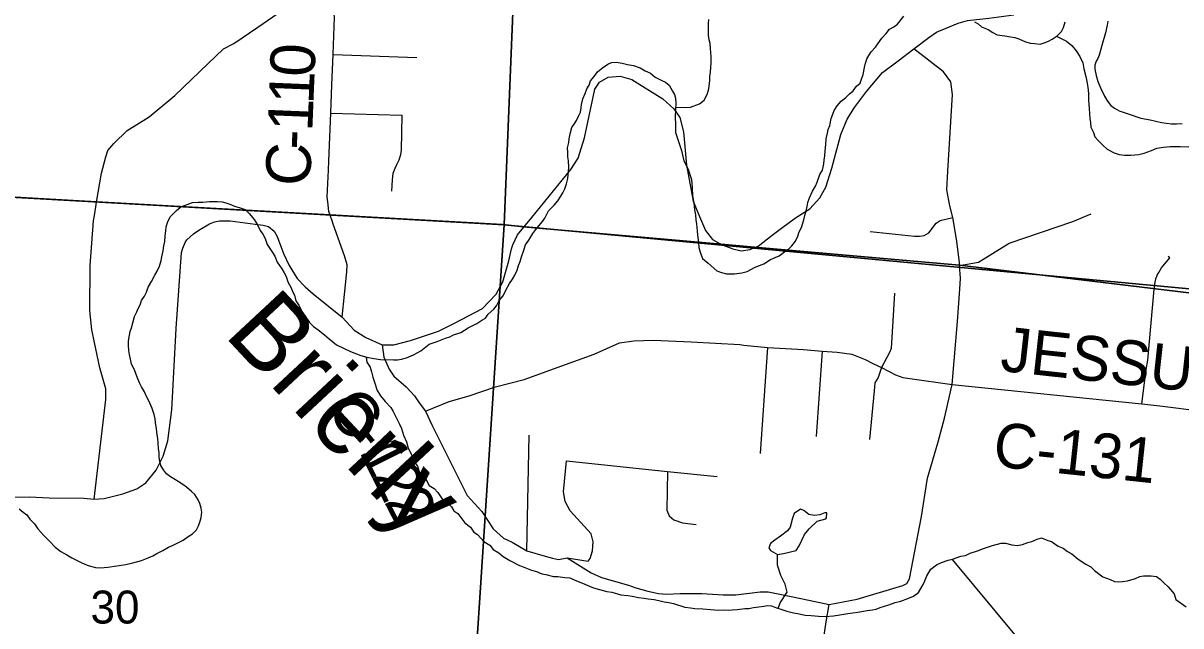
# Model space of a CAD drawing. Extents: x 0 to 34, y 0 to 22.
# Drawn here: x 6.66 to 8.131, y 16.534 to 17.301 of the extents above; entities that cross this region are included whole.
import ezdxf

# ---------------------------------------------------------------- set-up
doc = ezdxf.new("R2010")
doc.units = 0
for name, color, linetype in [('GM_X_County_Road', 7, 'Continuous'), ('GM_X_County_Road_Text', 7, 'Continuous'), ('GM_X_Minor_Lake', 7, 'Continuous'), ('GM_X_Minor_River', 7, 'Continuous'), ('GM_X_Minor_River_Text', 7, 'Continuous'), ('GM_X_Section', 7, 'Continuous'), ('GM_X_Section_Text', 7, 'Continuous'), ('GM_X_State_Route', 7, 'Continuous'), ('GM_X_Township_Road', 7, 'Continuous')]:
    doc.layers.add(name, color=color, linetype=linetype)

msp = doc.modelspace()

# ---------------------------------------------------------------- linework, layer by layer
at = {"layer": 'GM_X_County_Road'}
for points in [[(7.0481, 17.1255), (7.0507, 17.1859), (7.0521, 17.2223), (7.0536, 17.2608), (7.0555, 17.3082), (7.0537, 17.3227), (7.051, 17.3335)], [(6.752, 17.067), (6.753, 17.073), (6.759, 17.1097), (6.7646, 17.1304), (6.7671, 17.1386), (6.775, 17.1475), (6.7918, 17.1639), (6.8199, 17.1814), (6.8523, 17.2085), (6.8942, 17.249), (6.9143, 17.268), (6.9274, 17.2748), (6.958, 17.2954), (6.9892, 17.3172)], [(7.8237, 17.2902), (7.8331, 17.2941), (7.8482, 17.3004), (7.86, 17.3037), (7.8873, 17.3067), (7.9192, 17.3109)], [(8.0384, 17.303), (8.0378, 17.2981), (8.0356, 17.288), (8.0309, 17.2723), (8.0275, 17.2599), (8.0258, 17.2555), (8.0238, 17.2521), (8.0221, 17.2469), (8.0219, 17.242), (8.0236, 17.234), (8.0259, 17.2264), (8.0298, 17.2175), (8.0343, 17.2075), (8.0379, 17.2014), (8.0423, 17.1959), (8.047, 17.1924), (8.053, 17.1891), (8.0642, 17.1853), (8.0806, 17.1798), (8.0922, 17.1775), (8.1068, 17.174), (8.1196, 17.1724), (8.1257, 17.1726), (8.1332, 17.1731)], [(7.792, 17.2678), (7.8108, 17.2823), (7.8209, 17.289), (7.8237, 17.2902)], [(7.2806, 17.0137), (7.2819, 17.0188), (7.288, 17.0315), (7.296, 17.0411), (7.3061, 17.0533), (7.3559, 17.1144), (7.3651, 17.1289), (7.3731, 17.1548), (7.3865, 17.2167), (7.3921, 17.2256), (7.4033, 17.2317), (7.4185, 17.2331), (7.4332, 17.2289), (7.4726, 17.2044), (7.4866, 17.1915), (7.4945, 17.1806), (7.4989, 17.1622), (7.5028, 17.1199), (7.5112, 17.0741), (7.5196, 17.0548), (7.527, 17.0371), (7.5361, 17.0254), (7.5473, 17.019), (7.5619, 17.0136), (7.5724, 17.011), (7.5838, 17.0129), (7.5895, 17.0153), (7.5938, 17.0171), (7.6117, 17.031), (7.6238, 17.0397), (7.6413, 17.0532), (7.6598, 17.0644), (7.6724, 17.0784), (7.6801, 17.0922), (7.6877, 17.1162), (7.6989, 17.1588), (7.7072, 17.1783), (7.7164, 17.1932), (7.7318, 17.2136), (7.7519, 17.2376), (7.7721, 17.2525), (7.792, 17.2678)], [(7.8505, 16.9622), (7.8514, 16.9762), (7.8501, 16.9923), (7.8498, 16.9956), (7.8466, 17.0235), (7.8415, 17.0535), (7.8378, 17.0684), (7.8339, 17.0888), (7.8352, 17.1125), (7.8411, 17.21), (7.839, 17.226), (7.8297, 17.2386), (7.792, 17.2678)], [(7.0537, 17.0449), (7.0527, 17.0478), (7.0498, 17.0564), (7.0482, 17.0612), (7.0468, 17.0734), (7.0461, 17.0795), (7.0476, 17.1134), (7.0481, 17.1255)], [(6.7497, 16.6953), (6.7648, 16.822), (6.7645, 16.8357), (6.757, 16.8625), (6.7468, 16.9107), (6.7442, 16.9351), (6.7449, 16.9924), (6.7491, 17.0492), (6.7502, 17.056), (6.752, 17.067)], [(6.6459, 16.6978), (6.6675, 16.6983), (6.6928, 16.6971), (6.7368, 16.6968), (6.7497, 16.6953), (6.7626, 16.696), (6.7863, 16.7021), (6.8043, 16.7083), (6.8155, 16.7159), (6.8286, 16.7322), (6.8375, 16.7498), (6.8434, 16.7693), (6.8485, 16.809), (6.8542, 16.9122), (6.8611, 17.0088), (6.8628, 17.0144), (6.8654, 17.0218), (6.8676, 17.0252), (6.876, 17.0327), (6.8828, 17.0375), (6.8966, 17.0453), (6.903, 17.0481), (6.9093, 17.0493), (6.9229, 17.049), (6.9546, 17.0451), (6.9648, 17.0436), (6.9716, 17.0418), (6.9786, 17.0359), (6.9825, 17.0294), (6.9904, 17.0077), (6.9976, 16.9922), (7.0078, 16.976), (7.0183, 16.9654), (7.0282, 16.9565), (7.0653, 16.9268), (7.0806, 16.91), (7.0954, 16.9007), (7.1162, 16.8917)], [(7.0653, 16.9268), (7.0711, 16.9842), (7.0714, 16.9933), (7.068, 17.0048), (7.0537, 17.0449)], [(7.1162, 16.8917), (7.1308, 16.8917), (7.152, 16.897), (7.1875, 16.9091), (7.2078, 16.9191), (7.2436, 16.9376), (7.2609, 16.956), (7.2693, 16.9717), (7.2762, 16.9954), (7.2769, 16.9983), (7.2806, 17.0137)], [(7.5666, 16.3693), (7.5729, 16.382), (7.5835, 16.4001), (7.5945, 16.4148), (7.6108, 16.4342), (7.6302, 16.456), (7.6495, 16.4699), (7.6608, 16.4822), (7.6688, 16.4945), (7.6767, 16.5139), (7.6806, 16.5392), (7.6842, 16.5615), (7.7198, 16.568), (7.7777, 16.5855), (7.783, 16.588), (7.7863, 16.5939), (7.8017, 16.6732), (7.8094, 16.7219), (7.8227, 16.7682), (7.8308, 16.7983), (7.8406, 16.8413), (7.8479, 16.9261), (7.848, 16.9271), (7.8505, 16.9622)], [(7.1162, 16.8917), (7.1181, 16.8758), (7.1248, 16.8604), (7.131, 16.8518), (7.1467, 16.838), (7.1571, 16.8269), (7.1631, 16.8179), (7.1711, 16.8072), (7.1797, 16.7888), (7.2241, 16.7001), (7.2425, 16.6797), (7.2573, 16.6576), (7.2703, 16.6458), (7.2811, 16.6406), (7.3001, 16.6298), (7.3231, 16.623), (7.3327, 16.6202), (7.3402, 16.6184), (7.351, 16.6206), (7.3816, 16.6017), (7.3949, 16.5958), (7.4291, 16.586), (7.4386, 16.5827), (7.4539, 16.5783), (7.4671, 16.5753), (7.4775, 16.5747), (7.4947, 16.5753), (7.5225, 16.5755), (7.5493, 16.5735), (7.5654, 16.5736), (7.5967, 16.5776), (7.6069, 16.5775), (7.6235, 16.5741), (7.6584, 16.5669), (7.6842, 16.5615)], [(7.8406, 16.8413), (8.0817, 16.8164), (8.1046, 16.8141), (8.1583, 16.8073), (8.3231, 16.7946), (8.3586, 16.7977), (8.3922, 16.7964), (8.4414, 16.7983), (8.4714, 16.8008), (8.474, 16.8011), (8.4768, 16.8008), (8.4859, 16.7982), (8.5069, 16.7892), (8.6139, 16.7515), (8.6536, 16.7353), (8.699, 16.7148), (8.7733, 16.673), (8.8559, 16.6289)]]:
    msp.add_lwpolyline(points, dxfattribs=at)
at = {"layer": 'GM_X_Minor_Lake'}
for points in [[(7.6184, 16.625), (7.626, 16.6263), (7.6318, 16.6273), (7.6367, 16.6287), (7.6425, 16.6301), (7.646, 16.636), (7.6529, 16.6503), (7.6588, 16.6574), (7.6689, 16.6673), (7.68, 16.6705), (7.6808, 16.6716), (7.6813, 16.678), (7.6787, 16.6781), (7.6725, 16.6756), (7.6653, 16.6747), (7.6585, 16.676), (7.6522, 16.6811), (7.648, 16.6827), (7.6399, 16.6772), (7.6375, 16.6712), (7.6345, 16.6599), (7.6313, 16.655), (7.6224, 16.6484), (7.6151, 16.6433), (7.6096, 16.6389)], [(7.6096, 16.6389), (7.6076, 16.6336), (7.6098, 16.6302), (7.6184, 16.625)]]:
    msp.add_lwpolyline(points, dxfattribs=at)
at = {"layer": 'GM_X_Minor_River'}
for points in [[(7.489, 17.1901), (7.4883, 17.1814), (7.4887, 17.1715), (7.4891, 17.1613), (7.4904, 17.1563), (7.4967, 17.1386), (7.4996, 17.1255), (7.505, 17.1147), (7.5067, 17.1093), (7.5091, 17.1017), (7.5102, 17.091), (7.5106, 17.0811), (7.5122, 17.0719), (7.513, 17.0631), (7.5144, 17.057), (7.5149, 17.0505), (7.5158, 17.0448), (7.5163, 17.0364), (7.5169, 17.0311), (7.5181, 17.0219), (7.5186, 17.0154), (7.5203, 17.0093), (7.5234, 17.0012), (7.5304, 16.9953), (7.5415, 16.9858), (7.5475, 16.9837), (7.5539, 16.9819), (7.5638, 16.9816), (7.5733, 16.9831), (7.5802, 16.9848), (7.5903, 16.9902), (7.5957, 16.9926), (7.601, 16.9947), (7.6096, 17.0001), (7.6154, 17.0026), (7.6207, 17.0047), (7.6278, 17.0101), (7.6324, 17.013), (7.6368, 17.0174), (7.6415, 17.0233), (7.6444, 17.0297), (7.6461, 17.0353), (7.649, 17.0409), (7.6519, 17.0503), (7.6533, 17.056), (7.655, 17.062), (7.6563, 17.0673), (7.6573, 17.0726), (7.6594, 17.0786), (7.6631, 17.0868), (7.6667, 17.0932), (7.6688, 17.0984), (7.6725, 17.1082), (7.6758, 17.1137), (7.6776, 17.1217), (7.6781, 17.1262), (7.6787, 17.1319), (7.6793, 17.1383), (7.6799, 17.1463), (7.6806, 17.1535), (7.6823, 17.1606), (7.6829, 17.1652), (7.6849, 17.1704), (7.6868, 17.1791), (7.6888, 17.1847), (7.6905, 17.1896), (7.6945, 17.1956), (7.6993, 17.2015), (7.7055, 17.2062), (7.7102, 17.2106), (7.7149, 17.2146), (7.7189, 17.2206), (7.7236, 17.2242), (7.7253, 17.2295), (7.7274, 17.2351), (7.7292, 17.2441), (7.7306, 17.2498), (7.7327, 17.2562), (7.7375, 17.264), (7.743, 17.2699), (7.7462, 17.2743), (7.751, 17.2814), (7.7566, 17.2873), (7.7609, 17.2928), (7.7663, 17.2957), (7.771, 17.2993), (7.779, 17.3093)], [(7.4891, 17.1937), (7.502, 17.1931), (7.5081, 17.1937), (7.5196, 17.1978), (7.5255, 17.2026), (7.5291, 17.21), (7.5313, 17.2172), (7.5324, 17.2274), (7.5326, 17.2327), (7.5335, 17.238), (7.5337, 17.2445), (7.5343, 17.2498), (7.5342, 17.2581), (7.5334, 17.2684), (7.5329, 17.2745), (7.5319, 17.2795), (7.531, 17.2852), (7.5308, 17.2913), (7.5307, 17.3), (7.5313, 17.305)], [(7.8691, 17.3024), (7.8735, 17.2996), (7.878, 17.296), (7.8862, 17.2923), (7.8921, 17.2887), (7.8977, 17.2858), (7.9076, 17.2843), (7.9147, 17.2833), (7.9204, 17.2824), (7.9253, 17.2807), (7.9339, 17.2769), (7.9403, 17.2752), (7.9452, 17.2747), (7.9524, 17.274), (7.9574, 17.2754), (7.9631, 17.2775), (7.9678, 17.2803), (7.974, 17.2843), (7.9795, 17.2898), (7.982, 17.295), (7.9841, 17.3022)], [(7.9733, 17.2839), (7.9859, 17.2774), (7.9926, 17.2723), (7.9984, 17.2652), (8.0027, 17.2582), (8.0066, 17.2501), (8.0082, 17.2425), (8.0106, 17.2329), (8.0122, 17.2241), (8.0134, 17.2157), (8.014, 17.2103), (8.0141, 17.2027), (8.0148, 17.1921), (8.0154, 17.1852), (8.0155, 17.1791), (8.0165, 17.1738), (8.0167, 17.1684), (8.0202, 17.1615), (8.022, 17.1561), (8.0267, 17.151), (8.0322, 17.1455), (8.0377, 17.1403), (8.0467, 17.1355), (8.0531, 17.1337), (8.0595, 17.1327), (8.0678, 17.1325), (8.0778, 17.1336), (8.0846, 17.1353), (8.0939, 17.1388), (8.1008, 17.1416), (8.1092, 17.1428), (8.1176, 17.1437), (8.1305, 17.1436), (8.1415, 17.1432)], [(7.0179, 16.9279), (7.0237, 16.9201), (7.0288, 16.915), (7.0347, 16.9106), (7.0425, 16.9043), (7.0488, 16.8991), (7.058, 16.8916), (7.0677, 16.8867), (7.0759, 16.883), (7.0834, 16.88), (7.089, 16.8779), (7.0966, 16.8758), (7.1052, 16.874), (7.1139, 16.8729), (7.1302, 16.8723), (7.1355, 16.8725), (7.1405, 16.8731), (7.147, 16.8752), (7.1559, 16.8787), (7.1652, 16.884), (7.1757, 16.8924), (7.1861, 16.8959), (7.1965, 16.9001), (7.2019, 16.9018), (7.2065, 16.9043), (7.2161, 16.9074), (7.2254, 16.9131), (7.2362, 16.9188), (7.2428, 16.9228), (7.2475, 16.9253), (7.2507, 16.9305), (7.2581, 16.9367), (7.2613, 16.9411), (7.2646, 16.9479), (7.2697, 16.9538), (7.273, 16.9612), (7.2778, 16.9694), (7.2818, 16.975), (7.2847, 16.9802), (7.2875, 16.9866), (7.2893, 16.9926), (7.2913, 16.9975), (7.2931, 17.0035), (7.296, 17.0118), (7.2981, 17.0185), (7.3025, 17.0244), (7.3074, 17.033), (7.3113, 17.0382), (7.3153, 17.043), (7.3197, 17.0482), (7.3229, 17.0526), (7.3274, 17.062), (7.3348, 17.0689), (7.3392, 17.0745), (7.3432, 17.0804), (7.3456, 17.0849), (7.3481, 17.0898), (7.3502, 17.0961), (7.3519, 17.1029), (7.353, 17.112), (7.3532, 17.1173), (7.3527, 17.1253), (7.3521, 17.1307), (7.352, 17.1367), (7.3518, 17.1421), (7.3531, 17.1489), (7.3537, 17.1534), (7.355, 17.1598), (7.3572, 17.1677), (7.36, 17.1722), (7.3632, 17.1766), (7.3661, 17.183), (7.3681, 17.1875), (7.3691, 17.1928), (7.3696, 17.1973), (7.371, 17.2041), (7.3739, 17.2112), (7.376, 17.2169), (7.3792, 17.2217), (7.3809, 17.2273), (7.3853, 17.2325), (7.3896, 17.2388), (7.3963, 17.2439), (7.4029, 17.2482), (7.4075, 17.2503), (7.4136, 17.2509), (7.4211, 17.2495), (7.4279, 17.2481), (7.4355, 17.2467), (7.4441, 17.2438), (7.4504, 17.2397), (7.4572, 17.2368), (7.4631, 17.2317), (7.4716, 17.2276), (7.4761, 17.2255), (7.4809, 17.2216), (7.4849, 17.2142), (7.4877, 17.2096), (7.4891, 17.205), (7.4893, 17.1989), (7.489, 17.1901)], [(6.8866, 16.6786), (6.8857, 16.684), (6.8844, 16.6897), (6.8822, 16.6944), (6.8779, 16.7013), (6.8735, 16.7049), (6.8672, 16.7105), (6.8628, 16.714), (6.8565, 16.7177), (6.8513, 16.7213), (6.8468, 16.7237), (6.842, 16.7277), (6.838, 16.7327), (6.8348, 16.7382), (6.8334, 16.7435), (6.8325, 16.7481), (6.8323, 16.7542), (6.8317, 16.7599), (6.8312, 16.7664), (6.8307, 16.7725), (6.83, 16.7771), (6.8292, 16.7847), (6.8279, 16.7928), (6.8273, 16.7973), (6.826, 16.8031), (6.8236, 16.8104), (6.8212, 16.8165), (6.819, 16.8212), (6.8162, 16.8258), (6.8137, 16.8316), (6.8101, 16.8382), (6.8073, 16.8432), (6.8045, 16.8506), (6.801, 16.8598), (6.7975, 16.8668), (6.7962, 16.8733), (6.7949, 16.8794), (6.7939, 16.8844), (6.7934, 16.8912), (6.7935, 16.8958), (6.7945, 16.9018), (6.7955, 16.9086), (6.7972, 16.9131), (6.7989, 16.9195), (6.8011, 16.9274), (6.8039, 16.9334), (6.806, 16.9379), (6.8084, 16.9424), (6.8101, 16.9477), (6.8137, 16.9536), (6.8166, 16.9584), (6.8187, 16.9648), (6.8227, 16.9719), (6.8272, 16.9801), (6.83, 16.985), (6.8329, 16.9917), (6.835, 16.9989), (6.836, 17.0034), (6.8377, 17.0109), (6.8383, 17.0174), (6.8397, 17.023), (6.8403, 17.0302), (6.8409, 17.0366), (6.8414, 17.0416), (6.8436, 17.0483), (6.8468, 17.0547), (6.8547, 17.0624), (6.8602, 17.0668), (6.8679, 17.0699), (6.8748, 17.0723), (6.882, 17.0728), (6.8881, 17.073), (6.8965, 17.0739), (6.9067, 17.0739), (6.9124, 17.0733), (6.9173, 17.072), (6.9222, 17.0703), (6.9282, 17.0678), (6.9353, 17.0657), (6.9417, 17.0636), (6.9472, 17.058), (6.9534, 17.051), (6.9577, 17.044), (6.9609, 17.037), (6.9645, 17.0324), (6.9674, 17.0269), (6.9697, 17.0189), (6.9766, 17.0091), (6.9795, 17.0041), (6.9823, 16.9968), (6.9884, 16.9882), (6.9913, 16.9832), (6.9938, 16.9785), (6.9962, 16.9716), (7.0005, 16.9639), (7.0022, 16.9592), (7.0044, 16.9546), (7.0064, 16.9473), (7.0103, 16.9411), (7.0139, 16.9341), (7.0179, 16.9279)], [(7.0957, 16.876), (7.0967, 16.8697), (7.1007, 16.8631), (7.1024, 16.857), (7.104, 16.8504), (7.1061, 16.8439), (7.1095, 16.8335), (7.1138, 16.8269), (7.12, 16.8195), (7.127, 16.812), (7.1299, 16.8066), (7.1334, 16.8), (7.138, 16.7907), (7.1405, 16.7853), (7.1432, 16.7765), (7.1471, 16.7684), (7.1491, 16.7603), (7.1538, 16.7514), (7.1562, 16.7438), (7.1609, 16.7371), (7.1636, 16.7294), (7.171, 16.7216), (7.1756, 16.7127), (7.1819, 16.7087), (7.1867, 16.7039), (7.1928, 16.695), (7.198, 16.6921), (7.2043, 16.6855), (7.2071, 16.6804), (7.212, 16.6772), (7.221, 16.6651), (7.2284, 16.6596), (7.2324, 16.6533), (7.2372, 16.6505), (7.2453, 16.6415), (7.2527, 16.6367), (7.2571, 16.6312), (7.2641, 16.6272), (7.2697, 16.6224), (7.2782, 16.6172), (7.2905, 16.611), (7.2954, 16.6094), (7.3059, 16.6052), (7.3123, 16.6034), (7.319, 16.6006), (7.3239, 16.5996), (7.3337, 16.597), (7.3394, 16.5968), (7.3481, 16.5957), (7.3545, 16.5951), (7.3631, 16.5914), (7.3706, 16.5885), (7.3796, 16.5848), (7.3845, 16.5827), (7.3924, 16.5805), (7.4018, 16.5779), (7.4078, 16.577), (7.4195, 16.5739), (7.4282, 16.5728), (7.4338, 16.5719), (7.4418, 16.5705), (7.4489, 16.5695), (7.4542, 16.5685), (7.4618, 16.5679), (7.4678, 16.5665), (7.4746, 16.5648), (7.4803, 16.5638), (7.4863, 16.5625), (7.5006, 16.5582), (7.5081, 16.5571), (7.5134, 16.5562), (7.5236, 16.5558), (7.5335, 16.5551), (7.5437, 16.5544), (7.5506, 16.5545), (7.5559, 16.5544), (7.5608, 16.5546), (7.5677, 16.5551), (7.5772, 16.5563), (7.5821, 16.5565), (7.5879, 16.5574), (7.5947, 16.5583), (7.6012, 16.5592), (7.6062, 16.5602), (7.6111, 16.5597), (7.6171, 16.5572), (7.6227, 16.5555), (7.6306, 16.5529), (7.6389, 16.5507), (7.6438, 16.5498), (7.6536, 16.5479), (7.6615, 16.5473), (7.6706, 16.5466), (7.679, 16.5463), (7.6896, 16.5471), (7.698, 16.5483), (7.7079, 16.5498), (7.7205, 16.5517), (7.7324, 16.5536), (7.7392, 16.5545), (7.7442, 16.5554)], [(6.6544, 16.6829), (6.6596, 16.6789), (6.6641, 16.6753), (6.668, 16.6699), (6.6739, 16.664), (6.6783, 16.6577), (6.6859, 16.6491), (6.6929, 16.642), (6.7002, 16.6342), (6.7076, 16.6286), (6.7151, 16.6245), (6.7214, 16.6209), (6.7274, 16.6176), (6.7333, 16.6148), (6.7408, 16.6115), (6.7453, 16.6102), (6.7517, 16.6084), (6.7578, 16.6079), (6.7673, 16.6087), (6.7902, 16.6124), (6.799, 16.6144), (6.8101, 16.6174), (6.8186, 16.6209), (6.8244, 16.6234), (6.8294, 16.6263), (6.8371, 16.6302), (6.8445, 16.6341), (6.8503, 16.6369), (6.8564, 16.6398), (6.863, 16.6433), (6.8692, 16.6477), (6.8747, 16.6513), (6.8798, 16.6564), (6.8826, 16.6613), (6.8843, 16.6662), (6.8857, 16.6722), (6.8866, 16.6786)], [(7.7442, 16.5554), (7.7492, 16.5575), (7.76, 16.561), (7.768, 16.5641), (7.7753, 16.5657), (7.7842, 16.5689), (7.7915, 16.572), (7.7977, 16.5767), (7.8025, 16.5846), (7.805, 16.5894), (7.8083, 16.598), (7.8135, 16.6062), (7.8209, 16.6117), (7.8271, 16.6149), (7.8356, 16.6176), (7.8409, 16.6189), (7.8517, 16.6228), (7.8574, 16.6237), (7.8636, 16.6265), (7.8728, 16.6296), (7.8805, 16.6324), (7.892, 16.6362), (7.9031, 16.6392), (7.9085, 16.6394), (7.9164, 16.6372), (7.9232, 16.6366), (7.93, 16.6375), (7.9366, 16.6403), (7.9419, 16.6417), (7.9485, 16.6445), (7.9542, 16.6462), (7.9621, 16.6429), (7.967, 16.6416), (7.9755, 16.6356), (7.9819, 16.6331), (7.9871, 16.6287), (7.9927, 16.6258), (8.0008, 16.6191), (8.0104, 16.6127), (8.0168, 16.6094), (8.0215, 16.6047), (8.0323, 16.5967), (8.0413, 16.593), (8.0469, 16.5905), (8.0518, 16.5904), (8.0571, 16.5906), (8.0636, 16.5915), (8.0736, 16.5945), (8.079, 16.597), (8.0839, 16.598), (8.0934, 16.598), (8.1002, 16.597), (8.1051, 16.5935), (8.1098, 16.5891), (8.115, 16.584), (8.123, 16.575), (8.125, 16.5677), (8.138, 16.5585)], [(7.6194, 16.5565), (7.6221, 16.5637), (7.6308, 16.5772), (7.6284, 16.5871), (7.6226, 16.5983), (7.6184, 16.6113), (7.6184, 16.625)], [(7.8405, 16.6188), (7.9218, 16.5208)]]:
    msp.add_lwpolyline(points, dxfattribs=at)
at = {"layer": 'GM_X_Section'}
for points in [[(6.4651, 18.0799), (7.3111, 18.02), (7.2711, 17.0443), (6.3631, 17.0951)], [(7.3111, 18.02), (8.4694, 17.9573), (8.3778, 16.9409), (7.2711, 17.0443)], [(7.2711, 17.0443), (7.2064, 16.0507), (6.268, 16.1109), (6.3631, 17.0951)], [(7.2711, 17.0443), (8.3778, 16.9409), (8.2891, 15.9218), (7.2064, 16.0507)]]:
    msp.add_lwpolyline(points, close=True, dxfattribs=at)
at = {"layer": 'GM_X_State_Route'}
for points in [[(6.4637, 17.0899), (6.7527, 17.0735), (7.0496, 17.0569), (7.269, 17.0447), (7.2957, 17.0416), (7.547, 17.0195), (7.5893, 17.0158), (7.8498, 16.9928), (8.7245, 16.8871), (8.8708, 16.8659), (8.9, 16.8616), (8.9, 20.9)], [(8.9, 14.1), (8.9, 16.8616), (8.8708, 16.8659), (8.7245, 16.8871), (7.8498, 16.9928), (7.5893, 17.0158), (7.547, 17.0195), (7.2957, 17.0416), (7.269, 17.0447), (7.0496, 17.0569), (6.7527, 17.0735), (6.4637, 17.0899), (6.4015, 17.0935), (6.2997, 17.1032), (5.7668, 17.1675), (5.6871, 17.1709), (5.6621, 17.1734), (5.6544, 17.1743), (5.3786, 17.2047), (5.3, 16.4244), (5.2499, 15.926), (5.1715, 15.1469)]]:
    msp.add_lwpolyline(points, dxfattribs=at)
at = {"layer": 'GM_X_Township_Road'}
for p, q in [((7.0536, 17.2608), (7.16, 17.2567)), ((7.6057, 16.8881), (7.5966, 16.7535)), ((7.6755, 16.8833), (7.6678, 16.7751)), ((7.3001, 16.6298), (7.3027, 16.7765))]:
    msp.add_line(p, q, dxfattribs=at)
for points in [[(7.0507, 17.1859), (7.1409, 17.1837), (7.14, 17.139), (7.1395, 17.133), (7.1371, 17.1265), (7.1343, 17.1203), (7.132, 17.1158), (7.1295, 17.1093), (7.1285, 17.1015), (7.128, 17.087)], [(7.8501, 16.9923), (7.8741, 16.9968), (7.9131, 17.0207), (7.9942, 17.0485), (8.0173, 17.0579)], [(7.7362, 17.0358), (7.7929, 17.0298), (7.7991, 17.0298), (7.805, 17.0307), (7.8111, 17.0341), (7.8203, 17.0464), (7.8254, 17.0494), (7.8415, 17.0535)], [(8.0975, 16.9622), (8.0987, 16.9713), (8.0997, 16.9753), (8.1014, 16.9799), (8.1032, 16.9837), (8.1067, 16.9893), (8.1084, 16.9914), (8.1129, 16.9969), (8.1156, 17.0002), (8.1172, 17.0021), (8.115, 17.0039)], [(7.7674, 16.9572), (7.7632, 16.8867), (7.7611, 16.8819), (7.7571, 16.8745), (7.7509, 16.8626), (7.7465, 16.85), (7.7425, 16.8433), (7.7414, 16.8331), (7.7356, 16.771)], [(8.0817, 16.8164), (8.0871, 16.8601), (8.0892, 16.872), (8.0975, 16.9622)], [(7.1711, 16.8072), (7.2012, 16.8193), (7.2267, 16.8266), (7.26, 16.838), (7.2967, 16.8475), (7.3443, 16.8647), (7.3857, 16.8797), (7.4176, 16.894), (7.4358, 16.8965), (7.4604, 16.8973), (7.5086, 16.8955), (7.5708, 16.8918), (7.5758, 16.8913)], [(7.5758, 16.8913), (7.6057, 16.8881), (7.6515, 16.8856), (7.6755, 16.8833), (7.6945, 16.8823), (7.7129, 16.8797), (7.7301, 16.8727), (7.7407, 16.8672), (7.7509, 16.8626), (7.7605, 16.8577)], [(7.7605, 16.8577), (7.7686, 16.8535), (7.7779, 16.85), (7.7868, 16.8488), (7.8406, 16.8413)], [(7.351, 16.6206), (7.3779, 16.6165), (7.3804, 16.62), (7.3835, 16.6297), (7.3843, 16.6412), (7.3818, 16.6513), (7.3549, 16.6806), (7.3485, 16.6923), (7.3465, 16.7048), (7.3505, 16.744), (7.4788, 16.7307), (7.5417, 16.7241)], [(7.4788, 16.7307), (7.478, 16.6812), (7.481, 16.6743), (7.4868, 16.669), (7.4979, 16.6653), (7.5151, 16.663)]]:
    msp.add_lwpolyline(points, dxfattribs=at)

# ---------------------------------------------------------------- texts
at = {"layer": 'GM_X_County_Road_Text'}
for s, height, rotation, p in [('0', 0.0568, 87.6776, (7.0299, 17.2315)), ('1', 0.0568, 87.6502, (7.0285, 17.1968)), ('1', 0.0568, 87.6487, (7.0271, 17.1621)), ('-', 0.0568, 87.6481, (7.0261, 17.139)), ('C', 0.0568, 87.6069, (7.0242, 17.0927)), ('JESSUP', 0.05682, 353.7263, (7.9006, 16.8586)), ('C', 0.0568, 310.2596, (7.0432, 16.8068)), ('C-131', 0.05682, 353.9335, (7.891, 16.7373)), ('-', 0.0568, 309.5812, (7.0732, 16.7713)), ('1', 0.0568, 296.6686, (7.0862, 16.7562)), ('2', 0.0568, 296.2194, (7.1019, 16.725)), ('2', 0.0568, 297.2822, (7.1179, 16.6926))]:
    msp.add_text(s, height=height, rotation=rotation, dxfattribs=at).set_placement(p)
at = {"layer": 'GM_X_Minor_River_Text'}
msp.add_text('Brierly', height=0.0947, rotation=312.9898, dxfattribs=at).set_placement((6.9136, 16.9042))
at = {"layer": 'GM_X_Section_Text'}
msp.add_text('30', height=0.04186, rotation=0, dxfattribs=at).set_placement((6.7452, 16.5372))

doc.saveas('drawing.dxf')
